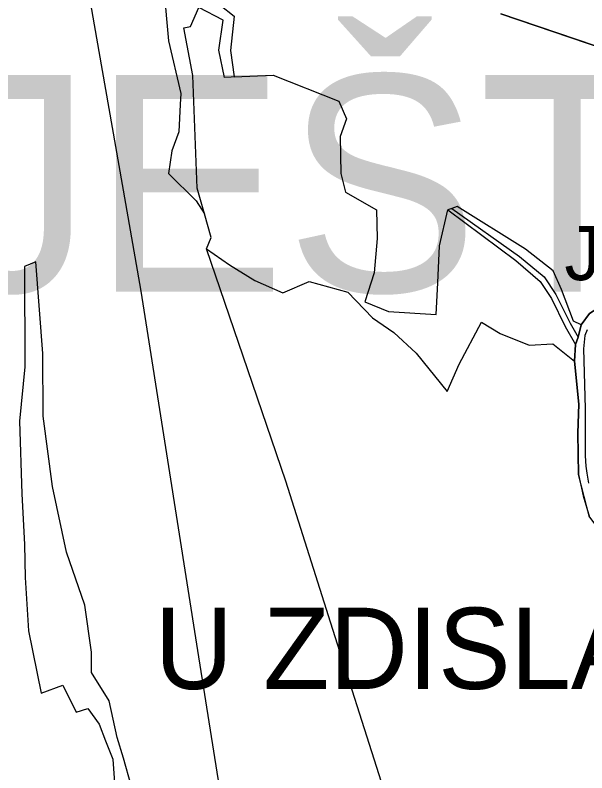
# Model space of a CAD drawing. Extents: x -706771 to -698463, y -971709 to -967107.
# Drawn here: x -701629 to -701207, y -970571 to -970012 of the extents above; entities that cross this region are included whole.
import ezdxf

# ---------------------------------------------------------------- set-up
doc = ezdxf.new("R2010")
doc.units = 0
for name, color, linetype in [('_hranice krajinny raz ochrana chrakteru zástavby KR2', 7, 'Continuous'), ('_KRAJINNY CELEK_popis', 7, 'Continuous'), ('_KRAJINNY OKRSEK', 7, 'Continuous'), ('_KRAJINNY OKRSEK_popis', 7, 'Continuous'), ('KN_Hranice_parcel', 7, 'Continuous'), ('Komunikace III třídy osy S', 7, 'Continuous'), ('Prvky nelesní zeleně_dominantní aleje', 7, 'Continuous'), ('Trasy cykloturistické S', 7, 'Continuous')]:
    doc.layers.add(name, color=color, linetype=linetype)

msp = doc.modelspace()

# ---------------------------------------------------------------- linework, layer by layer
at = {"layer": '_hranice krajinny raz ochrana chrakteru zástavby KR2'}
msp.add_line((-701270.23, -970010.59), (-701158.39, -970048.51), dxfattribs=at)
at = {"layer": '_KRAJINNY OKRSEK'}
for points in [[(-701270.23, -970010.59), (-701158.39, -970048.51), (-701170.45, -970103.6), (-701144.87, -970113.42)], [(-701158.39, -970048.51), (-701270.23, -970010.59)]]:
    msp.add_lwpolyline(points, dxfattribs=at)
at = {"layer": 'KN_Hranice_parcel'}
for p, q in [((-701306.44, -970154.22), (-701309.39, -970155.38)), ((-701210.91, -970240.11), (-701212.94, -970249.19)), ((-701212.94, -970249.19), (-701214.91, -970254.73)), ((-701214.91, -970254.73), (-701215.85, -970267.03))]:
    msp.add_line(p, q, dxfattribs=at)
for points in [[(-701526.66, -969966.94), (-701578.62, -969971.92), (-701567.02, -970038.33), (-701547.4, -970150.58), (-701536.08, -970215.38), (-701516.37, -970340.05), (-701494.15, -970480.58), (-701476.5, -970592.25), (-701462.72, -970679.4)], [(-701519.17, -969992.22), (-701515.67, -970030.42), (-701506.5, -970069.35), (-701506.94, -970077.49), (-701508.04, -970097.78), (-701513.25, -970111.59), (-701515.66, -970128.54), (-701495.11, -970148.63), (-701489.12, -970158.14)], [(-701477.63, -970004.02), (-701467.04, -970012.4), (-701469.75, -970037.61), (-701467.13, -970057.19)], [(-701489.12, -970158.14), (-701494.56, -970139.31), (-701497.66, -970056.19), (-701504.23, -970020.78), (-701499.47, -970019.83), (-701493.18, -970005.82)], [(-701467.13, -970057.19), (-701469.22, -970057.28), (-701474.17, -970057.5), (-701478.42, -970037.3), (-701475.13, -970015.27), (-701493.18, -970005.82)], [(-701467.13, -970057.19), (-701438.33, -970055.91), (-701389.84, -970075.15), (-701384.18, -970088.15), (-701388.71, -970101.04), (-701388.33, -970128.39), (-701385, -970142.19), (-701361.94, -970155.2), (-701361.57, -970176.37), (-701363.68, -970201.76), (-701370.68, -970223.16), (-701353.22, -970230.35), (-701317.85, -970232.54), (-701316.73, -970209.14), (-701315.34, -970181.94), (-701309.39, -970155.38)], [(-701309.39, -970155.38), (-701258.96, -970192.61), (-701241.11, -970208.27), (-701232.61, -970220.66), (-701222.59, -970241.53), (-701214.91, -970254.73)], [(-701210.91, -970240.11), (-701216.35, -970237.53), (-701225.21, -970214.15), (-701231.44, -970200.36), (-701251.99, -970184.21), (-701302.33, -970152.89), (-701306.44, -970154.22)], [(-701306.44, -970154.22), (-701256.37, -970189.75), (-701238.25, -970204.86), (-701229.61, -970217.77), (-701218.98, -970239.02), (-701212.94, -970249.19)], [(-701487.46, -970184.01), (-701484.05, -970175.7), (-701489.12, -970158.14)], [(-701152.94, -970170.36), (-701153.9, -970173.98), (-701158.35, -970197.4), (-701166.48, -970212.56), (-701175.77, -970218.04), (-701189.21, -970222.04), (-701204.65, -970231.9), (-701210.91, -970240.11)], [(-701327.99, -970673.83), (-701360.14, -970572.46), (-701394.19, -970465.05), (-701428.9, -970355.61), (-701456.97, -970273.35), (-701487.46, -970184.01)], [(-701487.46, -970184.01), (-701470.59, -970195.95), (-701451.94, -970207.39), (-701431.18, -970216.62), (-701411.83, -970208.12), (-701383.07, -970216.02), (-701364.86, -970234.98), (-701349.09, -970245.83), (-701332.66, -970261.2), (-701309.71, -970289.42), (-701300.86, -970269.11), (-701284.52, -970238.17), (-701270.55, -970246.58), (-701249.24, -970255.15), (-701231.75, -970254.24), (-701215.85, -970267.03)], [(-701543.25, -970580.42), (-701548.83, -970560.12), (-701553.52, -970544.99), (-701559.39, -970517.81), (-701572.51, -970496.88), (-701572.41, -970481.94), (-701577.42, -970447.2), (-701590.92, -970407.96), (-701601.41, -970359.44), (-701608.26, -970307.51), (-701608.43, -970261.42), (-701613.72, -970193.75), (-701621.97, -970197.03), (-701621.81, -970271.14), (-701625.71, -970311.27), (-701623.95, -970364.9), (-701621.99, -970402.43), (-701621.41, -970426.79), (-701619.04, -970466.16), (-701609.71, -970512.15), (-701593.59, -970506.35), (-701583.94, -970526.15), (-701575.11, -970523.35), (-701566.74, -970535.08), (-701562.26, -970547.36), (-701556.82, -970560.86), (-701555.3, -970581.8)], [(-701215.85, -970267.03), (-701212.48, -970298.73), (-701213.34, -970320.11), (-701212.68, -970350.78), (-701209.34, -970366.53), (-701204.68, -970382.2), (-701193.82, -970396.45), (-701165.95, -970428.78), (-701145.93, -970450.62), (-701138.17, -970458.17), (-701125.23, -970474.4), (-701115.81, -970490.14), (-701104.47, -970511.89), (-701097.52, -970524.93), (-701089.16, -970549.37), (-701071.25, -970598.78), (-701058.58, -970638.08), (-701052.15, -970658.25), (-701044.15, -970691.45), (-701034.1, -970728.35), (-701027.25, -970751.07), (-701018.71, -970773.3), (-701005.26, -970807.89), (-700998.89, -970828.17)]]:
    msp.add_lwpolyline(points, dxfattribs=at)
at = {"layer": 'Komunikace III třídy osy S'}
msp.add_lwpolyline([(-701206.41, -970243.97), (-701208.08, -970247.95), (-701209.12, -970257.97), (-701207.75, -970301.96), (-701207.88, -970329.42), (-701207.79, -970336.82), (-701207.25, -970344.47), (-701206.65, -970349.67), (-701205.36, -970357.21)], dxfattribs=at)
at = {"layer": 'Prvky nelesní zeleně_dominantní aleje'}
msp.add_lwpolyline([(-701210.91, -970240.11), (-701204.65, -970231.9), (-701189.21, -970222.04), (-701175.77, -970218.04), (-701166.48, -970212.56)], dxfattribs=at)
at = {"layer": 'Trasy cykloturistické S'}
msp.add_lwpolyline([(-701204.68, -970382.2), (-701212.68, -970350.78), (-701213.34, -970320.11), (-701212.48, -970298.73), (-701215.85, -970267.03), (-701214.91, -970254.73), (-701212.94, -970249.19), (-701210.91, -970240.11), (-701204.65, -970231.9)], dxfattribs=at)

# ---------------------------------------------------------------- texts
at = {"layer": '_KRAJINNY CELEK_popis'}
msp.add_text('11 - ZÁPADNÍ PODJEŠTĚDÍ', height=160, dxfattribs=at).set_placement((-703557.4, -970215.74))
at = {"layer": '_KRAJINNY OKRSEK_popis'}
msp.add_text('U ZDISLAVY', height=60, dxfattribs=at).set_placement((-701525.94, -970509.04))
at = {"layer": 'Prvky nelesní zeleně_dominantní aleje'}
msp.add_text('JS', height=40, dxfattribs=at).set_placement((-701223.16, -970207.21))

doc.saveas('drawing.dxf')
